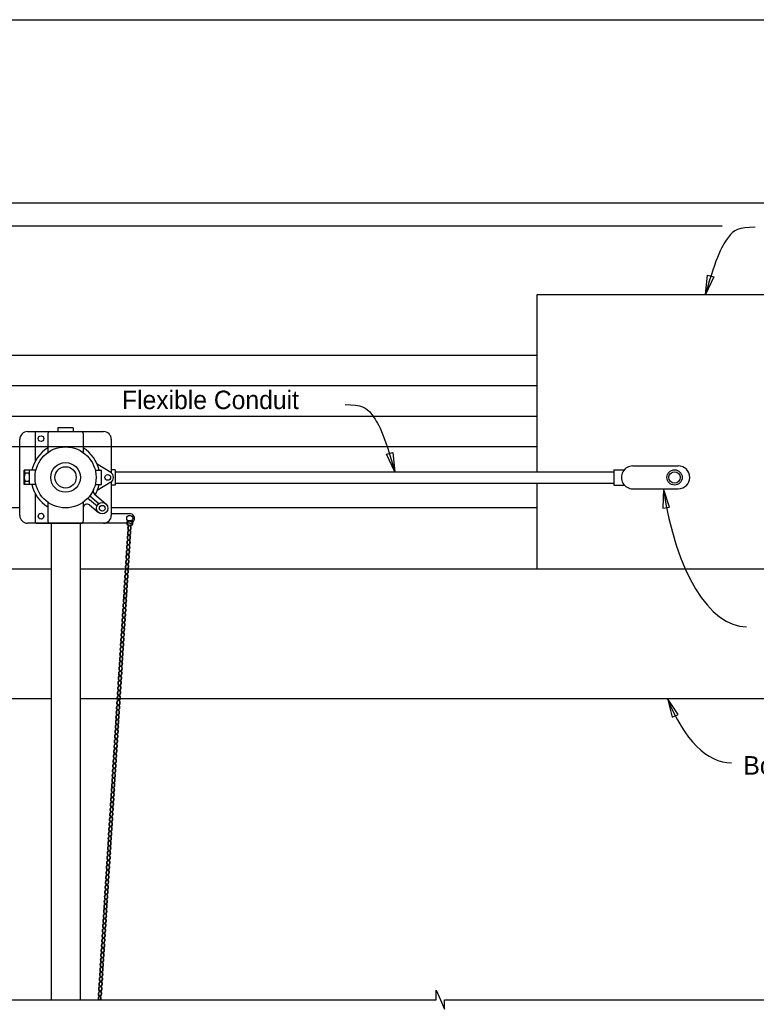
# Model space of a CAD drawing. Extents: x 0 to 20.5, y 0 to 13.
# Drawn here: x 7.91 to 11.94, y 3.07 to 8.47 of the extents above; entities that cross this region are included whole.
import ezdxf

# ---------------------------------------------------------------- set-up
doc = ezdxf.new("R2010")
doc.units = 0
for name, color, linetype in [('Dimension', 7, 'Continuous'), ('Miscellaneous', 7, 'Continuous'), ('NavLight', 7, 'Continuous'), ('NavLight_h', 7, 'Continuous'), ('SupstrConc', 7, 'Continuous'), ('TextStructures', 7, 'Continuous')]:
    doc.layers.add(name, color=color, linetype=linetype)

msp = doc.modelspace()

# ---------------------------------------------------------------- linework, layer by layer
at = {"layer": 'Dimension'}
for points in [[(11.7044, 7.0706), (11.6597, 6.9749), (11.6704, 7.0799)], [(9.9509, 6.1112), (9.9615, 6.0061), (9.9169, 6.1018)], [(11.4293, 5.9124), (11.4272, 5.8068), (11.4621, 5.812)], [(11.4513, 4.7665), (11.4782, 4.6644), (11.5104, 4.679)]]:
    msp.add_lwpolyline(points, close=True, dxfattribs=at)
msp.add_lwpolyline([(5.858, 3.1215), (10.1884, 3.1215), (10.1884, 3.1731), (10.2109, 3.1215), (10.2334, 3.0698), (10.2334, 3.1215), (13.9245, 3.1215)], dxfattribs=at)
for centre, start_param in [((11.877, 6.2637), 1.891817), ((11.794, 5.5203), 2.319085)]:
    msp.add_ellipse(centre, major_axis=(-0.007, 1.1046), ratio=0.429332, start_param=start_param, end_param=3.141574, dxfattribs=at)
for points in [[(11.9304, 7.3411), (11.8399, 7.3411), (11.791, 7.3121), (11.7175, 7.1845), (11.6597, 6.9749)], [(9.6909, 6.3724), (9.7813, 6.3724), (9.8302, 6.3433), (9.9037, 6.2158), (9.9615, 6.0061)]]:
    msp.add_open_spline(points, degree=3, dxfattribs=at)
at = {"layer": 'Miscellaneous'}
for radius in [0.0153, 0.0125]:
    msp.add_circle((8.5138, 5.7249), radius, dxfattribs=at)
for centre, major_axis, ratio in [((8.5105, 5.6726), (0.001, 0.0153), 0.530594), ((8.5122, 5.6991), (0.001, 0.0153), 0.530594), ((8.5105, 5.6726), (0.0008, 0.0133), 0.458548), ((8.5122, 5.6991), (0.0008, 0.0133), 0.458548), ((8.5071, 5.6196), (0.001, 0.0153), 0.530594), ((8.5088, 5.6461), (0.001, 0.0153), 0.530594), ((8.5071, 5.6196), (0.0008, 0.0133), 0.458548), ((8.5088, 5.6461), (0.0008, 0.0133), 0.458548), ((8.5038, 5.5666), (0.001, 0.0153), 0.530594), ((8.5054, 5.5931), (0.001, 0.0153), 0.530594), ((8.5038, 5.5666), (0.0008, 0.0133), 0.458548), ((8.5054, 5.5931), (0.0008, 0.0133), 0.458548), ((8.5004, 5.5135), (0.001, 0.0153), 0.530594), ((8.5021, 5.54), (0.001, 0.0153), 0.530594), ((8.5004, 5.5135), (0.0008, 0.0133), 0.458548), ((8.5021, 5.54), (0.0008, 0.0133), 0.458548), ((8.4971, 5.4605), (0.001, 0.0153), 0.530594), ((8.4987, 5.487), (0.001, 0.0153), 0.530594), ((8.4971, 5.4605), (0.0008, 0.0133), 0.458548), ((8.4987, 5.487), (0.0008, 0.0133), 0.458548), ((8.4937, 5.4075), (0.001, 0.0153), 0.530594), ((8.4954, 5.434), (0.001, 0.0153), 0.530594), ((8.4937, 5.4075), (0.0008, 0.0133), 0.458548), ((8.4954, 5.434), (0.0008, 0.0133), 0.458548), ((8.4903, 5.3545), (0.001, 0.0153), 0.530594), ((8.492, 5.381), (0.001, 0.0153), 0.530594), ((8.4903, 5.3545), (0.0008, 0.0133), 0.458548), ((8.492, 5.381), (0.0008, 0.0133), 0.458548), ((8.487, 5.3014), (0.001, 0.0153), 0.530594), ((8.4887, 5.3279), (0.001, 0.0153), 0.530594), ((8.487, 5.3014), (0.0008, 0.0133), 0.458548), ((8.4887, 5.3279), (0.0008, 0.0133), 0.458548), ((8.4836, 5.2484), (0.001, 0.0153), 0.530594), ((8.4853, 5.2749), (0.001, 0.0153), 0.530594), ((8.4836, 5.2484), (0.0008, 0.0133), 0.458548), ((8.4853, 5.2749), (0.0008, 0.0133), 0.458548), ((8.4803, 5.1954), (0.001, 0.0153), 0.530594), ((8.4819, 5.2219), (0.001, 0.0153), 0.530594), ((8.4803, 5.1954), (0.0008, 0.0133), 0.458548), ((8.4819, 5.2219), (0.0008, 0.0133), 0.458548), ((8.4769, 5.1423), (0.001, 0.0153), 0.530594), ((8.4786, 5.1689), (0.001, 0.0153), 0.530594), ((8.4769, 5.1423), (0.0008, 0.0133), 0.458548), ((8.4786, 5.1689), (0.0008, 0.0133), 0.458548), ((8.4736, 5.0893), (0.001, 0.0153), 0.530594), ((8.4752, 5.1158), (0.001, 0.0153), 0.530594), ((8.4736, 5.0893), (0.0008, 0.0133), 0.458548), ((8.4752, 5.1158), (0.0008, 0.0133), 0.458548), ((8.4702, 5.0363), (0.001, 0.0153), 0.530594), ((8.4719, 5.0628), (0.001, 0.0153), 0.530594), ((8.4702, 5.0363), (0.0008, 0.0133), 0.458548), ((8.4719, 5.0628), (0.0008, 0.0133), 0.458548), ((8.4668, 4.9833), (0.001, 0.0153), 0.530594), ((8.4685, 5.0098), (0.001, 0.0153), 0.530594), ((8.4668, 4.9833), (0.0008, 0.0133), 0.458548), ((8.4685, 5.0098), (0.0008, 0.0133), 0.458548), ((8.4618, 4.9037), (0.001, 0.0153), 0.530594), ((8.4635, 4.9302), (0.001, 0.0153), 0.530594), ((8.4652, 4.9567), (0.001, 0.0153), 0.530594), ((8.4635, 4.9302), (0.0008, 0.0133), 0.458548), ((8.4652, 4.9567), (0.0008, 0.0133), 0.458548), ((8.4584, 4.8507), (0.001, 0.0153), 0.530594), ((8.4601, 4.8772), (0.001, 0.0153), 0.530594), ((8.4601, 4.8772), (0.0008, 0.0133), 0.458548), ((8.4618, 4.9037), (0.0008, 0.0133), 0.458548), ((8.4551, 4.7977), (0.001, 0.0153), 0.530594), ((8.4568, 4.8242), (0.001, 0.0153), 0.530594), ((8.4551, 4.7977), (0.0008, 0.0133), 0.458548), ((8.4568, 4.8242), (0.0008, 0.0133), 0.458548), ((8.4584, 4.8507), (0.0008, 0.0133), 0.458548), ((8.4517, 4.7446), (0.001, 0.0153), 0.530594), ((8.4534, 4.7712), (0.001, 0.0153), 0.530594), ((8.4517, 4.7446), (0.0008, 0.0133), 0.458548), ((8.4534, 4.7712), (0.0008, 0.0133), 0.458548), ((8.4484, 4.6916), (0.001, 0.0153), 0.530594), ((8.4501, 4.7181), (0.001, 0.0153), 0.530594), ((8.4484, 4.6916), (0.0008, 0.0133), 0.458548), ((8.4501, 4.7181), (0.0008, 0.0133), 0.458548), ((8.445, 4.6386), (0.001, 0.0153), 0.530594), ((8.4467, 4.6651), (0.001, 0.0153), 0.530594), ((8.445, 4.6386), (0.0008, 0.0133), 0.458548), ((8.4467, 4.6651), (0.0008, 0.0133), 0.458548), ((8.4417, 4.5856), (0.001, 0.0153), 0.530594), ((8.4433, 4.6121), (0.001, 0.0153), 0.530594), ((8.4417, 4.5856), (0.0008, 0.0133), 0.458548), ((8.4433, 4.6121), (0.0008, 0.0133), 0.458548), ((8.4383, 4.5325), (0.001, 0.0153), 0.530594), ((8.44, 4.559), (0.001, 0.0153), 0.530594), ((8.4383, 4.5325), (0.0008, 0.0133), 0.458548), ((8.44, 4.559), (0.0008, 0.0133), 0.458548), ((8.435, 4.4795), (0.001, 0.0153), 0.530594), ((8.4366, 4.506), (0.001, 0.0153), 0.530594), ((8.435, 4.4795), (0.0008, 0.0133), 0.458548), ((8.4366, 4.506), (0.0008, 0.0133), 0.458548), ((8.4316, 4.4265), (0.001, 0.0153), 0.530594), ((8.4333, 4.453), (0.001, 0.0153), 0.530594), ((8.4316, 4.4265), (0.0008, 0.0133), 0.458548), ((8.4333, 4.453), (0.0008, 0.0133), 0.458548), ((8.4282, 4.3735), (0.001, 0.0153), 0.530594), ((8.4299, 4.4), (0.001, 0.0153), 0.530594), ((8.4282, 4.3735), (0.0008, 0.0133), 0.458548), ((8.4299, 4.4), (0.0008, 0.0133), 0.458548), ((8.4249, 4.3204), (0.001, 0.0153), 0.530594), ((8.4266, 4.3469), (0.001, 0.0153), 0.530594), ((8.4249, 4.3204), (0.0008, 0.0133), 0.458548), ((8.4266, 4.3469), (0.0008, 0.0133), 0.458548), ((8.4215, 4.2674), (0.001, 0.0153), 0.530594), ((8.4232, 4.2939), (0.001, 0.0153), 0.530594), ((8.4215, 4.2674), (0.0008, 0.0133), 0.458548), ((8.4232, 4.2939), (0.0008, 0.0133), 0.458548), ((8.4182, 4.2144), (0.001, 0.0153), 0.530594), ((8.4198, 4.2409), (0.001, 0.0153), 0.530594), ((8.4182, 4.2144), (0.0008, 0.0133), 0.458548), ((8.4198, 4.2409), (0.0008, 0.0133), 0.458548), ((8.4148, 4.1613), (0.001, 0.0153), 0.530594), ((8.4165, 4.1879), (0.001, 0.0153), 0.530594), ((8.4148, 4.1613), (0.0008, 0.0133), 0.458548), ((8.4165, 4.1879), (0.0008, 0.0133), 0.458548), ((8.4115, 4.1083), (0.001, 0.0153), 0.530594), ((8.4131, 4.1348), (0.001, 0.0153), 0.530594), ((8.4115, 4.1083), (0.0008, 0.0133), 0.458548), ((8.4131, 4.1348), (0.0008, 0.0133), 0.458548), ((8.4081, 4.0553), (0.001, 0.0153), 0.530594), ((8.4098, 4.0818), (0.001, 0.0153), 0.530594), ((8.4081, 4.0553), (0.0008, 0.0133), 0.458548), ((8.4098, 4.0818), (0.0008, 0.0133), 0.458548), ((8.4047, 4.0023), (0.001, 0.0153), 0.530594), ((8.4064, 4.0288), (0.001, 0.0153), 0.530594), ((8.4047, 4.0023), (0.0008, 0.0133), 0.458548), ((8.4064, 4.0288), (0.0008, 0.0133), 0.458548), ((8.4014, 3.9492), (0.001, 0.0153), 0.530594), ((8.4031, 3.9758), (0.001, 0.0153), 0.530594), ((8.4014, 3.9492), (0.0008, 0.0133), 0.458548), ((8.4031, 3.9758), (0.0008, 0.0133), 0.458548), ((8.398, 3.8962), (0.001, 0.0153), 0.530594), ((8.3997, 3.9227), (0.001, 0.0153), 0.530594), ((8.398, 3.8962), (0.0008, 0.0133), 0.458548), ((8.3997, 3.9227), (0.0008, 0.0133), 0.458548), ((8.3947, 3.8432), (0.001, 0.0153), 0.530594), ((8.3963, 3.8697), (0.001, 0.0153), 0.530594), ((8.3947, 3.8432), (0.0008, 0.0133), 0.458548), ((8.3963, 3.8697), (0.0008, 0.0133), 0.458548), ((8.3913, 3.7902), (0.001, 0.0153), 0.530594), ((8.393, 3.8167), (0.001, 0.0153), 0.530594), ((8.3913, 3.7902), (0.0008, 0.0133), 0.458548), ((8.393, 3.8167), (0.0008, 0.0133), 0.458548), ((8.388, 3.7371), (0.001, 0.0153), 0.530594), ((8.3896, 3.7636), (0.001, 0.0153), 0.530594), ((8.388, 3.7371), (0.0008, 0.0133), 0.458548), ((8.3896, 3.7636), (0.0008, 0.0133), 0.458548), ((8.3846, 3.6841), (0.001, 0.0153), 0.530594), ((8.3863, 3.7106), (0.001, 0.0153), 0.530594), ((8.3846, 3.6841), (0.0008, 0.0133), 0.458548), ((8.3863, 3.7106), (0.0008, 0.0133), 0.458548), ((8.3812, 3.6311), (0.001, 0.0153), 0.530594), ((8.3829, 3.6576), (0.001, 0.0153), 0.530594), ((8.3812, 3.6311), (0.0008, 0.0133), 0.458548), ((8.3829, 3.6576), (0.0008, 0.0133), 0.458548), ((8.3779, 3.578), (0.001, 0.0153), 0.530594), ((8.3796, 3.6046), (0.001, 0.0153), 0.530594), ((8.3779, 3.578), (0.0008, 0.0133), 0.458548), ((8.3796, 3.6046), (0.0008, 0.0133), 0.458548), ((8.3728, 3.4985), (0.001, 0.0153), 0.530594), ((8.3745, 3.525), (0.001, 0.0153), 0.530594), ((8.3762, 3.5515), (0.001, 0.0153), 0.530594), ((8.3745, 3.525), (0.0008, 0.0133), 0.458548), ((8.3762, 3.5515), (0.0008, 0.0133), 0.458548), ((8.3695, 3.4455), (0.001, 0.0153), 0.530594), ((8.3712, 3.472), (0.001, 0.0153), 0.530594), ((8.3712, 3.472), (0.0008, 0.0133), 0.458548), ((8.3728, 3.4985), (0.0008, 0.0133), 0.458548), ((8.3661, 3.3925), (0.001, 0.0153), 0.530594), ((8.3678, 3.419), (0.001, 0.0153), 0.530594), ((8.3661, 3.3925), (0.0008, 0.0133), 0.458548), ((8.3678, 3.419), (0.0008, 0.0133), 0.458548), ((8.3695, 3.4455), (0.0008, 0.0133), 0.458548), ((8.3628, 3.3394), (0.001, 0.0153), 0.530594), ((8.3645, 3.3659), (0.001, 0.0153), 0.530594), ((8.3628, 3.3394), (0.0008, 0.0133), 0.458548), ((8.3645, 3.3659), (0.0008, 0.0133), 0.458548), ((8.3594, 3.2864), (0.001, 0.0153), 0.530594), ((8.3611, 3.3129), (0.001, 0.0153), 0.530594), ((8.3594, 3.2864), (0.0008, 0.0133), 0.458548), ((8.3611, 3.3129), (0.0008, 0.0133), 0.458548), ((8.3561, 3.2334), (0.001, 0.0153), 0.530594), ((8.3577, 3.2599), (0.001, 0.0153), 0.530594), ((8.3561, 3.2334), (0.0008, 0.0133), 0.458548), ((8.3577, 3.2599), (0.0008, 0.0133), 0.458548), ((8.3527, 3.1803), (0.001, 0.0153), 0.530594), ((8.3544, 3.2069), (0.001, 0.0153), 0.530594), ((8.3527, 3.1803), (0.0008, 0.0133), 0.458548), ((8.3544, 3.2069), (0.0008, 0.0133), 0.458548), ((8.351, 3.1538), (0.001, 0.0153), 0.530594), ((8.351, 3.1538), (0.0008, 0.0133), 0.458548)]:
    msp.add_ellipse(centre, major_axis=major_axis, ratio=ratio, dxfattribs=at)
for major_axis, ratio, start_param, end_param in [((0.001, 0.0153), 0.530594, 4.3543, 8.279228), ((0.0008, 0.0133), 0.458548, 4.285385, 8.339029)]:
    msp.add_ellipse((8.3493, 3.1273), major_axis=major_axis, ratio=ratio, start_param=start_param, end_param=end_param, dxfattribs=at)
at = {"layer": 'NavLight'}
for p, q in [((8.0066, 6.2249), (8.2491, 6.2249)), ((8.2046, 6.2457), (8.1213, 6.2457)), ((8.1213, 6.2457), (8.1213, 6.2249)), ((8.2046, 6.2457), (8.2046, 6.2249)), ((7.9962, 6.2145), (7.9962, 6.0607)), ((8.0665, 6.2145), (8.0665, 6.1108)), ((8.2595, 6.2145), (8.2595, 6.1107)), ((8.0011, 6.0144), (7.9376, 6.0144)), ((7.9376, 5.9353), (7.9376, 6.0144)), ((7.9669, 5.9353), (7.9669, 6.0144)), ((8.3249, 6.0144), (8.359, 6.0144)), ((8.4099, 6.0014), (8.3361, 6.0468)), ((8.359, 5.9353), (8.359, 6.0144)), ((8.4338, 6.0165), (8.4129, 6.0165)), ((8.4338, 6.0165), (8.4338, 5.9332)), ((8.4338, 6.0061), (11.1589, 6.0061)), ((11.1589, 6.0165), (11.1589, 5.9332)), ((11.1589, 6.0165), (11.2156, 6.0165)), ((11.2622, 6.0374), (11.5106, 6.0374)), ((7.9623, 5.9974), (7.9423, 5.9974)), ((7.9623, 5.953), (7.9423, 5.953)), ((8.4099, 5.9483), (8.3361, 5.9029)), ((8.0011, 5.9353), (7.9376, 5.9353)), ((8.3249, 5.9353), (8.359, 5.9353)), ((8.4338, 5.9332), (8.4129, 5.9332)), ((8.4338, 5.9436), (11.1589, 5.9436)), ((11.1589, 5.9332), (11.2156, 5.9332)), ((11.2622, 5.9124), (11.5106, 5.9124)), ((7.9962, 5.889), (7.9962, 5.7353)), ((8.0665, 5.8389), (8.0665, 5.7353)), ((8.2595, 5.839), (8.2595, 5.7353)), ((8.2855, 5.8618), (8.3353, 5.82)), ((8.2955, 5.8738), (8.3453, 5.832)), ((8.321, 5.883), (8.3835, 5.8305)), ((8.2937, 5.8244), (8.3434, 5.7827)), ((8.0066, 5.7249), (8.2491, 5.7249)), ((8.0838, 5.7248), (8.0838, 3.1215)), ((8.2421, 5.7248), (8.2421, 3.1215))]:
    msp.add_line(p, q, dxfattribs=at)
for points in [[(7.9546, 6.2249), (8.3712, 6.2249)], [(7.9129, 5.7666), (7.9129, 6.1832)], [(8.4129, 6.1832), (8.4129, 5.9996)], [(8.4129, 5.9502), (8.4129, 5.7666)], [(8.4129, 5.777), (8.5138, 5.777)], [(8.5138, 5.7249), (7.9546, 5.7249)]]:
    msp.add_lwpolyline(points, dxfattribs=at)
for centre, radius in [((8.0289, 6.1866), 0.0156), ((8.1629, 5.9749), 0.1667), ((8.1629, 5.9749), 0.081), ((8.1629, 5.9749), 0.0582), ((8.3935, 5.9749), 0.0156), ((8.3635, 5.8066), 0.0312), ((8.3635, 5.8066), 0.0156), ((8.0289, 5.7631), 0.0156), ((8.5138, 5.7509), 0.0168)]:
    msp.add_circle(centre, radius, dxfattribs=at)
for centre, radius, start, end in [((7.9546, 6.1832), 0.0417, 90, 180), ((8.0066, 6.2145), 0.0104, 90, 180), ((8.0769, 6.2145), 0.0104, 90, 180), ((8.2491, 6.2145), 0.0104, 0, 90), ((8.3712, 6.1832), 0.0417, 0, 90), ((8.1629, 5.9749), 0.1875, 120.9603, 167.8245), ((8.1629, 5.9749), 0.1875, 12.1755, 58.984), ((7.9835, 6.0177), 0.0461, 184.249, 206.2673), ((7.9209, 6.0177), 0.0461, 333.7327, 355.751), ((8.3935, 5.9749), 0.0312, 301.564, 58.4266), ((11.2622, 5.9749), 0.0625, 90, 270.0068), ((11.5106, 5.9749), 0.0625, 270, 89.9875), ((7.993, 5.9751), 0.0554, 156.4172, 203.5828), ((7.9835, 5.9326), 0.0461, 153.7327, 175.751), ((7.9114, 5.9751), 0.0554, 336.4172, 23.5828), ((7.9209, 5.9326), 0.0461, 4.249, 26.2673), ((8.1629, 5.9749), 0.1875, 192.1669, 239.0397), ((8.3344, 5.8989), 0.0208, 156.1011, 230), ((8.1629, 5.9749), 0.1875, 329.5786, 347.8331), ((8.2803, 5.8085), 0.0208, 50, 180), ((7.9546, 5.7666), 0.0417, 180, 270), ((8.0066, 5.7353), 0.0104, 180, 270), ((8.0769, 5.7353), 0.0104, 180, 270), ((8.2491, 5.7353), 0.0104, 270, 360), ((8.3712, 5.7666), 0.0417, 270, 360), ((8.5138, 5.7509), 0.026, 269.9996, 90.0525)]:
    msp.add_arc(centre, radius, start, end, dxfattribs=at)
at = {"layer": 'NavLight_h'}
for p, q in [((10.7406, 6.6416), (5.858, 6.6416)), ((10.7406, 6.4749), (5.858, 6.4749)), ((10.7406, 6.3082), (5.858, 6.3082)), ((10.7406, 6.1415), (5.858, 6.1415)), ((7.9129, 5.8082), (5.858, 5.8082)), ((10.7406, 5.8082), (8.4129, 5.8082))]:
    msp.add_line(p, q, dxfattribs=at)
for radius in [0.0416, 0.0312]:
    msp.add_circle((11.4906, 5.9749), radius, dxfattribs=at)
at = {"layer": 'SupstrConc'}
for p, q in [((5.858, 8.4748), (13.9245, 8.4748)), ((5.858, 7.4748), (13.9245, 7.4748)), ((5.858, 7.3498), (11.7507, 7.3498)), ((10.7406, 6.9749), (12.2406, 6.9749)), ((10.7406, 6.0061), (10.7406, 6.9749)), ((10.7406, 5.4749), (10.7406, 5.9436)), ((5.858, 5.4749), (8.0838, 5.4749)), ((8.2421, 5.4749), (13.9245, 5.4749)), ((10.7406, 5.4749), (12.2406, 5.4749)), ((5.858, 4.7666), (8.0838, 4.7666)), ((8.2421, 4.7666), (13.9245, 4.7666))]:
    msp.add_line(p, q, dxfattribs=at)

# ---------------------------------------------------------------- texts
at = {"layer": 'TextStructures'}
for s, p in [('Flexible Conduit', (8.4714, 6.348)), ('Bottom of Bridge Deck', (11.8665, 4.3514))]:
    msp.add_text(s, height=0.1008, dxfattribs=at).set_placement(p)

doc.saveas('drawing.dxf')
